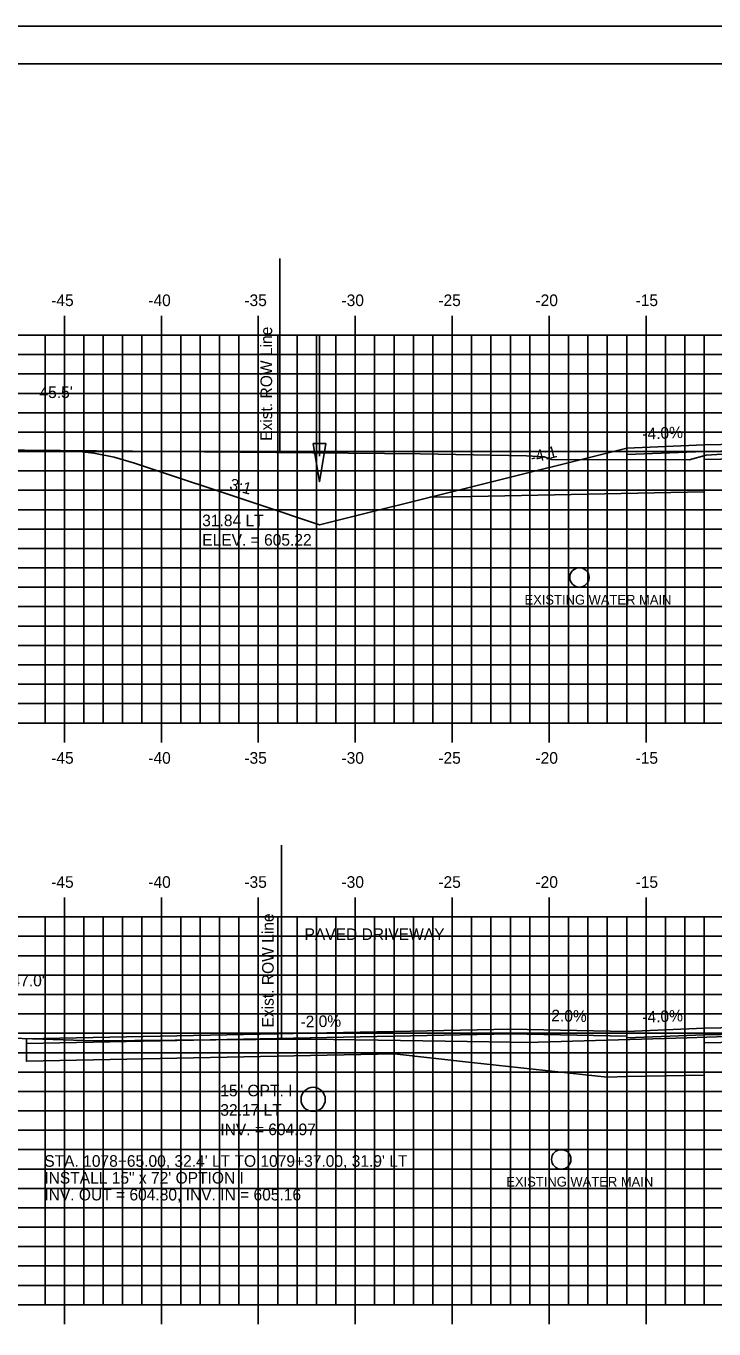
# Model space of a CAD drawing. Extents: x 1070760 to 1070930, y 779716 to 779826.
# Drawn here: x 1070795.9 to 1070831.4, y 779758.5 to 779825.6 of the extents above; entities that cross this region are included whole.
import ezdxf

# ---------------------------------------------------------------- set-up
doc = ezdxf.new("R2010")
doc.units = 0
for name, color, linetype in [('ANNOTATION', 7, 'Continuous'), ('BORDER', 7, 'Continuous'), ('D_Drainage_Culvert', 7, 'Continuous'), ('D_Drainage_Ditch_Line', 7, 'Continuous'), ('D_Roadway_Centerline', 7, 'Continuous'), ('D_Roadway_Centerline_Text', 7, 'Continuous'), ('D_Roadway_Drive_Paved', 7, 'Continuous'), ('D_Roadway_Drive_SubGrade', 7, 'Continuous'), ('D_Roadway_Edge_Pavement', 7, 'Continuous'), ('D_Roadway_Edge_Shoulder', 7, 'Continuous'), ('D_Roadway_Pavement', 7, 'Continuous'), ('D_Roadway_SlopeLines', 7, 'Continuous'), ('D_Roadway_SubGrade', 7, 'Continuous'), ('D_Text_Monospaced', 7, 'Continuous'), ('D_Text_Standard', 7, 'Continuous'), ('E_ROW_Line', 7, 'Continuous'), ('Existing Water Main', 7, 'Continuous'), ('H_V ANNOTATION', 7, 'Continuous'), ('MAJOR', 7, 'Continuous'), ('MINOR', 7, 'Continuous'), ('PLOT BOUNDARY', 7, 'Continuous'), ('S_Roadway_Centerline', 7, 'Continuous')]:
    doc.layers.add(name, color=color, linetype=linetype)

msp = doc.modelspace()

# ---------------------------------------------------------------- linework, layer by layer
at = {"layer": 'BORDER'}
msp.add_lwpolyline([(1070767.881, 779718.706), (1070927.881, 779718.706), (1070927.881, 779823.706), (1070767.881, 779823.706)], close=True, dxfattribs=at)
at = {"layer": 'D_Drainage_Culvert'}
msp.add_circle((1070810.709, 779770.294), 0.625, dxfattribs=at)
at = {"layer": 'D_Drainage_Ditch_Line'}
msp.add_line((1070811.037, 779803.462), (1070811.038, 779809.706), dxfattribs=at)
msp.add_lwpolyline([(1070810.709, 779804.118), (1070811.365, 779804.118), (1070811.037, 779802.15)], close=True, dxfattribs=at)
at = {"layer": 'D_Roadway_Centerline'}
msp.add_lwpolyline([(1070826.881, 779773.806), (1070830.881, 779773.966), (1070842.881, 779774.206), (1070854.881, 779773.966), (1070858.881, 779773.806)], dxfattribs=at)
at = {"layer": 'D_Roadway_Drive_Paved'}
for points in [[(1070826.881, 779773.806), (1070820.881, 779773.926), (1070795.921, 779773.427)], [(1070826.881, 779773.556), (1070820.881, 779773.676), (1070795.921, 779773.177)]]:
    msp.add_lwpolyline(points, dxfattribs=at)
at = {"layer": 'D_Roadway_Drive_SubGrade'}
for points in [[(1070826.881, 779803.886), (1070811.038, 779799.926)], [(1070826.881, 779803.886), (1070826.881, 779803.553), (1070830.881, 779803.713), (1070830.881, 779801.63), (1070818.881, 779801.39), (1070816.721, 779801.347)], [(1070795.921, 779773.427), (1070795.921, 779772.26), (1070814.881, 779772.639), (1070818.881, 779772.207)], [(1070826.881, 779771.469), (1070825.881, 779771.449), (1070818.881, 779772.207)], [(1070825.881, 779771.449), (1070826.881, 779771.469)]]:
    msp.add_lwpolyline(points, dxfattribs=at)
at = {"layer": 'D_Roadway_Edge_Pavement'}
for points in [[(1070830.881, 779803.713), (1070830.881, 779804.046), (1070842.881, 779804.286), (1070854.881, 779804.046), (1070854.881, 779803.713), (1070842.881, 779803.953)], [(1070830.881, 779773.633), (1070830.881, 779773.966), (1070842.881, 779774.206), (1070854.881, 779773.966), (1070854.881, 779773.633), (1070842.881, 779773.873)]]:
    msp.add_lwpolyline(points, close=True, dxfattribs=at)
at = {"layer": 'D_Roadway_Edge_Shoulder'}
for points in [[(1070830.881, 779804.046), (1070826.881, 779803.886), (1070826.881, 779803.553), (1070830.881, 779803.713)], [(1070830.881, 779773.966), (1070826.881, 779773.806), (1070826.881, 779773.473), (1070830.881, 779773.633)]]:
    msp.add_lwpolyline(points, close=True, dxfattribs=at)
at = {"layer": 'D_Roadway_Pavement'}
for points in [[(1070830.881, 779803.296), (1070830.881, 779803.713), (1070842.881, 779803.953), (1070854.881, 779803.713), (1070854.881, 779803.296), (1070842.881, 779803.536)], [(1070830.881, 779773.216), (1070830.881, 779773.633), (1070842.881, 779773.873), (1070854.881, 779773.633), (1070854.881, 779773.216), (1070842.881, 779773.456)]]:
    msp.add_lwpolyline(points, close=True, dxfattribs=at)
at = {"layer": 'D_Roadway_SlopeLines'}
msp.add_line((1070811.038, 779799.926), (1070807.862, 779800.984), dxfattribs=at)
msp.add_lwpolyline([(1070807.862, 779800.984), (1070801.492, 779803.108), (1070800.438, 779803.414), (1070799.397, 779803.625), (1070798.37, 779803.742), (1070797.357, 779803.765)], dxfattribs=at)
at = {"layer": 'D_Roadway_SubGrade'}
msp.add_lwpolyline([(1070830.881, 779771.549), (1070826.881, 779771.469), (1070826.881, 779773.806), (1070826.881, 779773.473), (1070830.881, 779773.633), (1070830.881, 779773.633), (1070830.881, 779772.133)], close=True, dxfattribs=at)
msp.add_lwpolyline([(1070830.881, 779771.549), (1070826.881, 779771.469), (1070826.881, 779773.806), (1070826.881, 779773.473), (1070830.881, 779773.633), (1070830.881, 779773.633), (1070830.881, 779772.133)], close=True, dxfattribs=at)
at = {"layer": 'E_ROW_Line'}
for p, q in [((1070808.993, 779803.657), (1070808.993, 779813.657)), ((1070808.993, 779803.657), (1070808.993, 779813.657)), ((1070809.075, 779773.402), (1070809.075, 779783.402)), ((1070809.075, 779773.402), (1070809.075, 779783.402))]:
    msp.add_line(p, q, dxfattribs=at)
at = {"layer": 'Existing Water Main'}
for points in [[(1070824.444, 779797.214), (1070824.444, 779797.214)], [(1070823.505, 779767.203), (1070823.505, 779767.203)]]:
    msp.add_lwpolyline(points, dxfattribs=at)
for centre in [(1070824.444, 779797.214), (1070823.505, 779767.203)]:
    msp.add_circle(centre, 0.501, dxfattribs=at)
at = {"layer": 'MAJOR'}
for p, q in [((1070797.881, 779810.708), (1070797.881, 779809.706)), ((1070802.881, 779810.708), (1070802.881, 779809.706)), ((1070807.881, 779810.708), (1070807.881, 779809.706)), ((1070812.881, 779810.708), (1070812.881, 779809.706)), ((1070817.881, 779810.708), (1070817.881, 779809.706)), ((1070822.881, 779810.708), (1070822.881, 779809.706)), ((1070827.881, 779810.708), (1070827.881, 779809.706)), ((1070772.881, 779809.706), (1070912.881, 779809.706)), ((1070772.881, 779809.706), (1070912.881, 779809.706)), ((1070797.881, 779789.706), (1070797.881, 779809.706)), ((1070802.881, 779789.706), (1070802.881, 779809.706)), ((1070807.881, 779789.706), (1070807.881, 779809.706)), ((1070812.881, 779789.706), (1070812.881, 779809.706)), ((1070817.881, 779789.706), (1070817.881, 779809.706)), ((1070822.881, 779789.706), (1070822.881, 779809.706)), ((1070827.881, 779789.706), (1070827.881, 779809.706)), ((1070772.881, 779804.706), (1070912.881, 779804.706)), ((1070772.881, 779799.706), (1070912.881, 779799.706)), ((1070772.881, 779794.706), (1070912.881, 779794.706)), ((1070772.881, 779789.706), (1070912.881, 779789.706)), ((1070772.881, 779789.706), (1070912.881, 779789.706)), ((1070797.881, 779788.704), (1070797.881, 779789.706)), ((1070802.881, 779788.704), (1070802.881, 779789.706)), ((1070807.881, 779788.704), (1070807.881, 779789.706)), ((1070812.881, 779788.704), (1070812.881, 779789.706)), ((1070817.881, 779788.704), (1070817.881, 779789.706)), ((1070822.881, 779788.704), (1070822.881, 779789.706)), ((1070827.881, 779788.704), (1070827.881, 779789.706)), ((1070797.881, 779780.708), (1070797.881, 779779.706)), ((1070802.881, 779780.708), (1070802.881, 779779.706)), ((1070807.881, 779780.708), (1070807.881, 779779.706)), ((1070812.881, 779780.708), (1070812.881, 779779.706)), ((1070817.881, 779780.708), (1070817.881, 779779.706)), ((1070822.881, 779780.708), (1070822.881, 779779.706)), ((1070827.881, 779780.708), (1070827.881, 779779.706)), ((1070772.881, 779779.706), (1070912.881, 779779.706)), ((1070772.881, 779779.706), (1070912.881, 779779.706)), ((1070797.881, 779759.706), (1070797.881, 779779.706)), ((1070802.881, 779759.706), (1070802.881, 779779.706)), ((1070807.881, 779759.706), (1070807.881, 779779.706)), ((1070812.881, 779759.706), (1070812.881, 779779.706)), ((1070817.881, 779759.706), (1070817.881, 779779.706)), ((1070822.881, 779759.706), (1070822.881, 779779.706)), ((1070827.881, 779759.706), (1070827.881, 779779.706)), ((1070772.881, 779774.706), (1070912.881, 779774.706)), ((1070772.881, 779769.706), (1070912.881, 779769.706)), ((1070772.881, 779764.706), (1070912.881, 779764.706)), ((1070772.881, 779759.706), (1070912.881, 779759.706)), ((1070772.881, 779759.706), (1070912.881, 779759.706)), ((1070797.881, 779758.704), (1070797.881, 779759.706)), ((1070802.881, 779758.704), (1070802.881, 779759.706)), ((1070807.881, 779758.704), (1070807.881, 779759.706)), ((1070812.881, 779758.704), (1070812.881, 779759.706)), ((1070817.881, 779758.704), (1070817.881, 779759.706)), ((1070822.881, 779758.704), (1070822.881, 779759.706)), ((1070827.881, 779758.704), (1070827.881, 779759.706))]:
    msp.add_line(p, q, dxfattribs=at)
at = {"layer": 'MINOR'}
for p, q in [((1070796.881, 779789.706), (1070796.881, 779809.706)), ((1070798.881, 779789.706), (1070798.881, 779809.706)), ((1070799.881, 779789.706), (1070799.881, 779809.706)), ((1070800.881, 779789.706), (1070800.881, 779809.706)), ((1070801.881, 779789.706), (1070801.881, 779809.706)), ((1070803.881, 779789.706), (1070803.881, 779809.706)), ((1070804.881, 779789.706), (1070804.881, 779809.706)), ((1070805.881, 779789.706), (1070805.881, 779809.706)), ((1070806.881, 779789.706), (1070806.881, 779809.706)), ((1070808.881, 779789.706), (1070808.881, 779809.706)), ((1070809.881, 779789.706), (1070809.881, 779809.706)), ((1070810.881, 779789.706), (1070810.881, 779809.706)), ((1070811.881, 779789.706), (1070811.881, 779809.706)), ((1070813.881, 779789.706), (1070813.881, 779809.706)), ((1070814.881, 779789.706), (1070814.881, 779809.706)), ((1070815.881, 779789.706), (1070815.881, 779809.706)), ((1070816.881, 779789.706), (1070816.881, 779809.706)), ((1070818.881, 779789.706), (1070818.881, 779809.706)), ((1070819.881, 779789.706), (1070819.881, 779809.706)), ((1070820.881, 779789.706), (1070820.881, 779809.706)), ((1070821.881, 779789.706), (1070821.881, 779809.706)), ((1070823.881, 779789.706), (1070823.881, 779809.706)), ((1070824.881, 779789.706), (1070824.881, 779809.706)), ((1070825.881, 779789.706), (1070825.881, 779809.706)), ((1070826.881, 779789.706), (1070826.881, 779809.706)), ((1070828.881, 779789.706), (1070828.881, 779809.706)), ((1070829.881, 779789.706), (1070829.881, 779809.706)), ((1070830.881, 779789.706), (1070830.881, 779809.706)), ((1070772.881, 779808.706), (1070912.881, 779808.706)), ((1070772.881, 779807.706), (1070912.881, 779807.706)), ((1070772.881, 779806.706), (1070912.881, 779806.706)), ((1070772.881, 779805.706), (1070912.881, 779805.706)), ((1070772.881, 779803.706), (1070912.881, 779803.706)), ((1070772.881, 779802.706), (1070912.881, 779802.706)), ((1070772.881, 779801.706), (1070912.881, 779801.706)), ((1070772.881, 779800.706), (1070912.881, 779800.706)), ((1070772.881, 779798.706), (1070912.881, 779798.706)), ((1070772.881, 779797.706), (1070912.881, 779797.706)), ((1070772.881, 779796.706), (1070912.881, 779796.706)), ((1070772.881, 779795.706), (1070912.881, 779795.706)), ((1070772.881, 779793.706), (1070912.881, 779793.706)), ((1070772.881, 779792.706), (1070912.881, 779792.706)), ((1070772.881, 779791.706), (1070912.881, 779791.706)), ((1070772.881, 779790.706), (1070912.881, 779790.706)), ((1070796.881, 779759.706), (1070796.881, 779779.706)), ((1070798.881, 779759.706), (1070798.881, 779779.706)), ((1070799.881, 779759.706), (1070799.881, 779779.706)), ((1070800.881, 779759.706), (1070800.881, 779779.706)), ((1070801.881, 779759.706), (1070801.881, 779779.706)), ((1070803.881, 779759.706), (1070803.881, 779779.706)), ((1070804.881, 779759.706), (1070804.881, 779779.706)), ((1070805.881, 779759.706), (1070805.881, 779779.706)), ((1070806.881, 779759.706), (1070806.881, 779779.706)), ((1070808.881, 779759.706), (1070808.881, 779779.706)), ((1070809.881, 779759.706), (1070809.881, 779779.706)), ((1070810.881, 779759.706), (1070810.881, 779779.706)), ((1070811.881, 779759.706), (1070811.881, 779779.706)), ((1070813.881, 779759.706), (1070813.881, 779779.706)), ((1070814.881, 779759.706), (1070814.881, 779779.706)), ((1070815.881, 779759.706), (1070815.881, 779779.706)), ((1070816.881, 779759.706), (1070816.881, 779779.706)), ((1070818.881, 779759.706), (1070818.881, 779779.706)), ((1070819.881, 779759.706), (1070819.881, 779779.706)), ((1070820.881, 779759.706), (1070820.881, 779779.706)), ((1070821.881, 779759.706), (1070821.881, 779779.706)), ((1070823.881, 779759.706), (1070823.881, 779779.706)), ((1070824.881, 779759.706), (1070824.881, 779779.706)), ((1070825.881, 779759.706), (1070825.881, 779779.706)), ((1070826.881, 779759.706), (1070826.881, 779779.706)), ((1070828.881, 779759.706), (1070828.881, 779779.706)), ((1070829.881, 779759.706), (1070829.881, 779779.706)), ((1070830.881, 779759.706), (1070830.881, 779779.706)), ((1070772.881, 779778.706), (1070912.881, 779778.706)), ((1070772.881, 779777.706), (1070912.881, 779777.706)), ((1070772.881, 779776.706), (1070912.881, 779776.706)), ((1070772.881, 779775.706), (1070912.881, 779775.706)), ((1070772.881, 779773.706), (1070912.881, 779773.706)), ((1070772.881, 779772.706), (1070912.881, 779772.706)), ((1070772.881, 779771.706), (1070912.881, 779771.706)), ((1070772.881, 779770.706), (1070912.881, 779770.706)), ((1070772.881, 779768.706), (1070912.881, 779768.706)), ((1070772.881, 779767.706), (1070912.881, 779767.706)), ((1070772.881, 779766.706), (1070912.881, 779766.706)), ((1070772.881, 779765.706), (1070912.881, 779765.706)), ((1070772.881, 779763.706), (1070912.881, 779763.706)), ((1070772.881, 779762.706), (1070912.881, 779762.706)), ((1070772.881, 779761.706), (1070912.881, 779761.706)), ((1070772.881, 779760.706), (1070912.881, 779760.706))]:
    msp.add_line(p, q, dxfattribs=at)
at = {"layer": 'PLOT BOUNDARY'}
msp.add_lwpolyline([(1070759.787, 779715.646), (1070929.787, 779715.646), (1070929.787, 779825.646), (1070759.787, 779825.646)], close=True, dxfattribs=at)
at = {"layer": 'S_Roadway_Centerline'}
for points in [[(1070772.881, 779803.721), (1070774.175, 779803.646), (1070777.601, 779803.698), (1070794.884, 779803.789), (1070795.54, 779803.781), (1070795.827, 779803.779), (1070816.237, 779803.59), (1070821.709, 779803.487), (1070822.62, 779803.428), (1070823.003, 779803.302), (1070830.109, 779803.275), (1070830.982, 779803.524), (1070832.895, 779803.63), (1070835.892, 779803.736), (1070842.927, 779803.871), (1070852.337, 779803.482), (1070852.341, 779803.484), (1070854.761, 779803.388), (1070858.356, 779803.244), (1070867.532, 779803.1)], [(1070772.881, 779774.132), (1070773.759, 779774.112), (1070779.811, 779773.957), (1070795.702, 779773.434), (1070799.41, 779773.309), (1070809.871, 779773.41), (1070810.603, 779773.404), (1070817.517, 779773.299), (1070820.921, 779773.247), (1070821.733, 779773.235), (1070830.005, 779773.474), (1070833.041, 779773.581), (1070833.041, 779773.583), (1070839.844, 779773.731), (1070843.179, 779773.795), (1070847.377, 779773.621), (1070854.88, 779773.288), (1070856.403, 779773.079), (1070857.709, 779773.049), (1070859.705, 779773.099), (1070862.196, 779772.901), (1070862.981, 779772.884), (1070865.676, 779772.98), (1070870.023, 779773.443)]]:
    msp.add_lwpolyline(points, dxfattribs=at)

# ---------------------------------------------------------------- texts
at = {"layer": 'ANNOTATION'}
for s, rotation, p in [('-4.0%', 2.29061, (1070827.697, 779804.32)), ('-4:1', 14.03624, (1070821.993, 779803.095)), ('3:1', 345.96376, (1070806.358, 779801.752)), ('2.0%', 358.78587, (1070822.987, 779774.325)), ('-4.0%', 2.29061, (1070827.697, 779774.24)), ('-2.0%', 1.14576, (1070810.061, 779774.004))]:
    msp.add_text(s, height=0.6, rotation=rotation, dxfattribs=at).set_placement(p)
for s, p in [('31.84 LT', (1070804.987, 779799.853)), ('ELEV. = 605.22', (1070804.987, 779798.851)), ('15" OPT. I', (1070805.92, 779770.455)), ('32.17 LT', (1070805.92, 779769.453)), ('INV. = 604.97', (1070805.92, 779768.451))]:
    msp.add_text(s, height=0.6, dxfattribs=at).set_placement(p)
at = {"layer": 'D_Roadway_Centerline_Text'}
for s, p in [("STA. 1078+65.00, 32.4' LT TO 1079+37.00, 31.9' LT", (1070796.842, 779766.82)), ('INSTALL 15" x 72\' OPTION I', (1070796.842, 779765.953)), ('INV. OUT = 604.80, INV. IN = 605.16', (1070796.842, 779765.086))]:
    msp.add_text(s, height=0.6, dxfattribs=at).set_placement(p)
at = {"layer": 'D_Text_Monospaced'}
for p in [(1070821.611, 779795.814), (1070820.671, 779765.803)]:
    msp.add_text('EXISTING WATER MAIN', height=0.49998, dxfattribs=at).set_placement(p)
at = {"layer": 'D_Text_Standard'}
for s, p in [("-45.5'", (1070796.326, 779806.465)), ('PAVED DRIVEWAY', (1070810.263, 779778.517)), ("-47.0'", (1070794.886, 779776.127))]:
    msp.add_text(s, height=0.6, dxfattribs=at).set_placement(p)
at = {"layer": 'E_ROW_Line'}
for p in [(1070808.593, 779804.257), (1070808.675, 779774.002)]:
    msp.add_text('Exist. ROW Line', height=0.6, rotation=90, dxfattribs=at).set_placement(p)
at = {"layer": 'H_V ANNOTATION'}
for s, p in [('-45', (1070797.198, 779811.206)), ('-40', (1070802.206, 779811.206)), ('-35', (1070807.161, 779811.206)), ('-30', (1070812.169, 779811.206)), ('-25', (1070817.166, 779811.206)), ('-20', (1070822.174, 779811.206)), ('-15', (1070827.337, 779811.206)), ('-45', (1070797.198, 779787.606)), ('-40', (1070802.206, 779787.606)), ('-35', (1070807.161, 779787.606)), ('-30', (1070812.169, 779787.606)), ('-25', (1070817.166, 779787.606)), ('-20', (1070822.174, 779787.606)), ('-15', (1070827.337, 779787.606)), ('-45', (1070797.198, 779781.206)), ('-40', (1070802.206, 779781.206)), ('-35', (1070807.161, 779781.206)), ('-30', (1070812.169, 779781.206)), ('-25', (1070817.166, 779781.206)), ('-20', (1070822.174, 779781.206)), ('-15', (1070827.337, 779781.206))]:
    msp.add_text(s, height=0.6, dxfattribs=at).set_placement(p)

doc.saveas('drawing.dxf')
